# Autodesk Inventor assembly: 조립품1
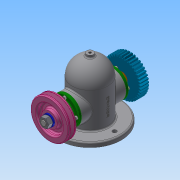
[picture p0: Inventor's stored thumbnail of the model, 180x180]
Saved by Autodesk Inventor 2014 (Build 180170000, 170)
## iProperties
Created: 2019-11
Part Number: 조립품1
Document SubType Name: Assembly
Designer: net
Author: net
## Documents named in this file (14)
- C:\Users\net\Desktop\491104V1051\조립품1.iam
- C:\Users\net\Desktop\491104V1051\본체.ipt
- C:\Users\net\Desktop\491104V1051\베어링 6203.ipt
- C:\Users\net\Desktop\491104V1051\커버.ipt
- C:\Users\net\Desktop\491104V1051\축.ipt
- C:\Users\net\Desktop\491104V1051\오일 실 26 38 8.ipt
- C:\Users\net\Desktop\491104V1051\볼트 M4.ipt
- C:\Users\net\Desktop\491104V1051\부시.ipt
- C:\Users\net\Desktop\491104V1051\키 5x5x12.ipt
- C:\Users\net\Desktop\491104V1051\스퍼기어.ipt
- C:\Users\net\Desktop\491104V1051\V-벨트풀리.ipt
- V-벨트풀리.ipt
- C:\Users\net\Desktop\491104V1051\와셔 12x24.ipt
- C:\Users\net\Desktop\491104V1051\너트 M12x1.25.ipt
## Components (1 placed, 1 different names)
1. V-벨트풀리:1
